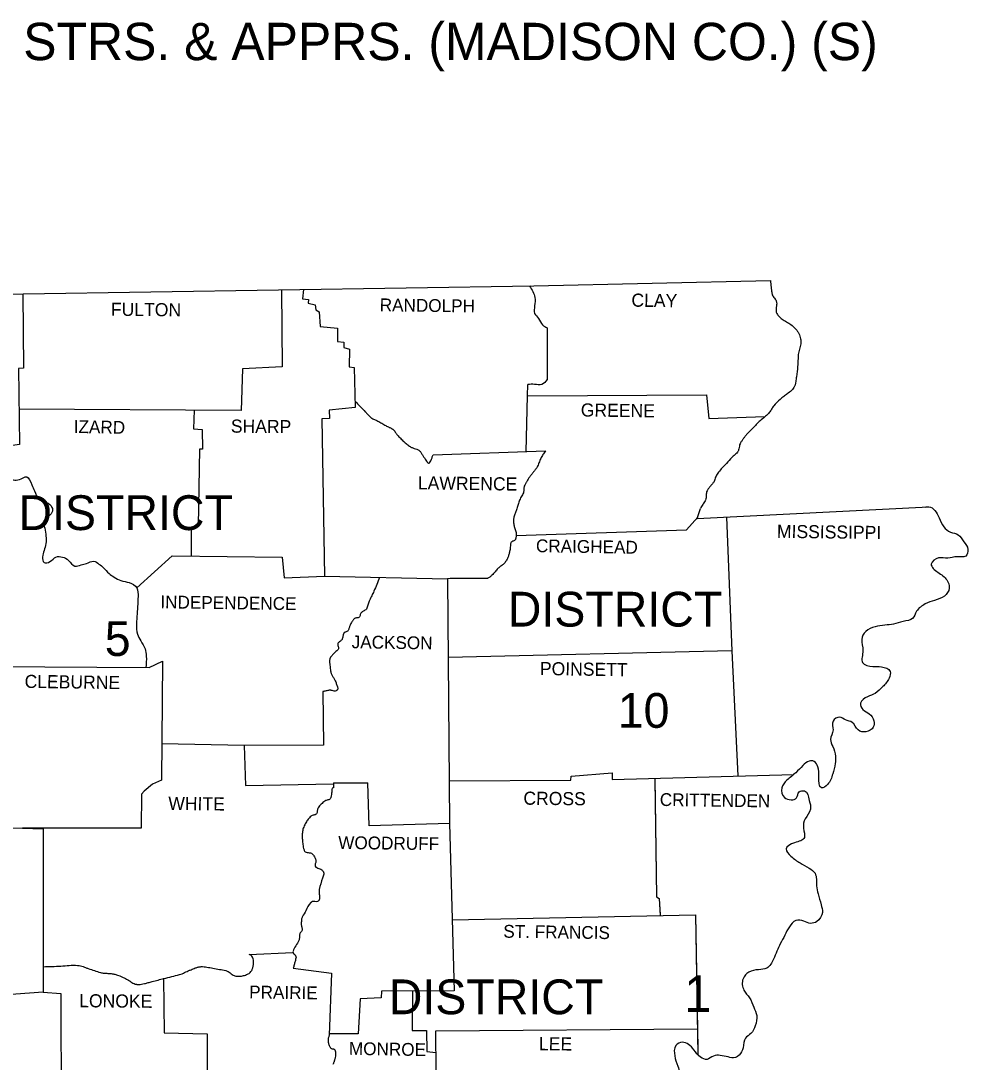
# Model space of a CAD drawing. Extents: x 0 to 3171, y 0 to 2059.
# Drawn here: x 2824.1 to 3134.6, y 1635.7 to 1977.1 of the extents above; entities that cross this region are included whole.
import ezdxf

# ---------------------------------------------------------------- set-up
doc = ezdxf.new("R2010")
doc.units = 0
doc.layers.add('Level 1', color=7, linetype='Continuous')

msp = doc.modelspace()

# ---------------------------------------------------------------- linework, layer by layer
at = {"layer": 'Level 1'}
for p, q in [((2990.18, 1854.23), (2990.27, 1857.93)), ((3045.77, 1813.93), (3046.85, 1817.25)), ((2926.57, 1727.34), (2937.75, 1727.34))]:
    msp.add_line(p, q, dxfattribs=at)
for points in [[(2521.17, 1887.43), (2682.87, 1887.33), (2824.77, 1887.63), (2992.17, 1890.23), (3069.77, 1892.03)], [(2909.47, 1888.95), (2909.67, 1863.73), (2896.67, 1863.03), (2896.27, 1849.43), (2823.43, 1849.84)], [(2916.75, 1889.06), (2916.37, 1886.03), (2918.37, 1885.73), (2918.27, 1884.53), (2920.57, 1884.03), (2920.77, 1882.43), (2921.87, 1881.73), (2922.17, 1876.93), (2927.87, 1876.33), (2927.87, 1872.03), (2929.97, 1871.73), (2929.97, 1870.03), (2931.77, 1869.53), (2931.67, 1863.73), (2933.27, 1863.43), (2933.67, 1850.33), (2925.17, 1849.53), (2925.27, 1846.73), (2922.67, 1846.63), (2923.57, 1795.04), (2963.87, 1794.14), (2964.57, 1713.94), (2938.27, 1713.24), (2937.75, 1727.34)], [(2824.76, 1887.63), (2824.97, 1863.23), (2823.27, 1863.13), (2823.57, 1838.23), (2816.57, 1837.23), (2817.17, 1830.53), (2819.57, 1827.43), (2819.37, 1819.53), (2805.77, 1819.03), (2805.27, 1806.83), (2792.87, 1806.44), (2792.27, 1791.64), (2792.97, 1790.44), (2793.27, 1766.84), (2814.67, 1765.44), (2814.37, 1712.74), (2831.37, 1712.24), (2831.37, 1658.64), (2817.97, 1657.64), (2816.97, 1645.84), (2794.47, 1645.74)], [(2996.57, 1876.43), (2996.57, 1859.53)], [(2989.74, 1835.91), (2990.18, 1854.23), (2990.27, 1854.23), (3048.77, 1854.53), (3049.57, 1846.73), (3067.92, 1847.4)], [(2880.88, 1849.52), (2880.67, 1843.33), (2883.47, 1843.13), (2883.57, 1836.73), (2882.57, 1836.73), (2882.17, 1811.53), (2879.87, 1810.53), (2879.87, 1801.65)], [(2959.17, 1834.83), (2996.04, 1836.13)], [(3045.77, 1813.93), (3121.67, 1817.83)], [(2986.43, 1808.42), (3042.27, 1810.23), (3045.94, 1814.46)], [(3055.35, 1814.43), (3057.07, 1770.54), (3059.1, 1729.57)], [(2862.06, 1791.25), (2873.67, 1801.74), (2909.67, 1801.24), (2910.37, 1794.54), (2923.57, 1795.04)], [(2976.97, 1794.34), (2964.77, 1794.34), (2963.87, 1794.14)], [(3057.07, 1770.54), (2964.09, 1768.42)], [(2814.67, 1765.44), (2866.07, 1765.14), (2870.47, 1767.24), (2870.17, 1728.14), (2867.17, 1726.84), (2864.47, 1724.54), (2863.57, 1723.64), (2863.47, 1712.44), (2824.57, 1712.44)], [(2923.07, 1757.24), (2923.27, 1739.64), (2897.27, 1739.54), (2870.26, 1740.04)], [(2897.27, 1739.54), (2897.67, 1726.44), (2926.57, 1726.95)], [(2964.45, 1727.93), (3004.37, 1728.14), (3004.47, 1729.54), (3017.87, 1730.54), (3017.87, 1728.44), (3077.44, 1730.07)], [(3031.86, 1728.82), (3032.37, 1689.94), (3033.27, 1689.34), (3033.59, 1683.8)], [(3031.87, 1728.44), (3032.37, 1689.94), (3033.27, 1689.34), (3033.57, 1684.14)], [(3031.87, 1728.44), (3032.37, 1689.94), (3033.27, 1689.34), (3033.57, 1684.14)], [(3031.87, 1728.44), (3032.37, 1689.94), (3033.27, 1689.34), (3033.57, 1684.14)], [(3031.87, 1728.44), (3032.37, 1689.94), (3033.27, 1689.34), (3033.57, 1684.14)], [(2926.57, 1727.34), (2926.57, 1725.64), (2926.07, 1725.54)], [(2964.57, 1713.94), (2966.07, 1659.14), (2942.27, 1659.04), (2942.17, 1656.84), (2935.27, 1656.44), (2934.67, 1645.04), (2925.19, 1645.04)], [(2965.43, 1682.43), (3045.17, 1684.04)], [(3045.17, 1684.04), (3045.97, 1640.24)], [(3045.17, 1684.04), (3045.97, 1640.24)], [(3045.17, 1684.04), (3045.97, 1640.24)], [(3045.17, 1684.04), (3045.97, 1640.24)], [(3045.17, 1684.04), (3045.97, 1640.24)], [(3045.17, 1684.04), (3045.97, 1640.24)], [(3045.17, 1684.04), (3045.97, 1640.24)], [(3045.17, 1684.04), (3046.01, 1638.23)], [(2898.87, 1671.04), (2913.26, 1671.73)], [(2913.37, 1666.54), (2925.87, 1664.94), (2925.17, 1644.54)], [(2870.87, 1663.24), (2871.07, 1645.34), (2885.17, 1645.04), (2885.27, 1606.64)], [(2831.37, 1658.64), (2837.17, 1658.24), (2837.27, 1620.04), (2832.07, 1598.34), (2843.17, 1597.84), (2843.07, 1578.73)], [(2952.47, 1659.08), (2952.37, 1646.14), (2956.97, 1646.14), (2957.17, 1639.24), (2960.12, 1638.93)], [(2964.24, 1557.34), (2973.57, 1557.94), (2973.47, 1578.24), (2966.17, 1578.74), (2966.57, 1618.44), (2960.27, 1619.34), (2960.07, 1646.04), (3045.85, 1646.64)]]:
    msp.add_lwpolyline(points, dxfattribs=at)
for points in [[(3069.77, 1892.03), (3069.86, 1890.93), (3069.97, 1889.83), (3070.11, 1888.73), (3070.27, 1887.63), (3070.5, 1887.01), (3070.91, 1886.45), (3071.34, 1885.91), (3071.67, 1885.33), (3071.8, 1884.32), (3071.67, 1883.22), (3071.6, 1882.13), (3071.67, 1881.62), (3071.87, 1881.13), (3072.63, 1880.15), (3073.57, 1879.33), (3074.28, 1878.86), (3075.02, 1878.44), (3075.76, 1878.02), (3076.47, 1877.53), (3077.91, 1876.25), (3078.53, 1875.51), (3078.81, 1875.09), (3079.07, 1874.63), (3079.43, 1873.79), (3079.64, 1872.93), (3079.72, 1872.08), (3079.67, 1871.23), (3079.5, 1870.36), (3079.25, 1869.49), (3079.01, 1868.62), (3078.87, 1867.73), (3078.81, 1866.76), (3078.78, 1865.79), (3078.74, 1864.81), (3078.67, 1863.83), (3078.27, 1860.43), (3078.08, 1858.87), (3077.93, 1858.1), (3077.81, 1857.71), (3077.67, 1857.33), (3076.63, 1855.95), (3075.27, 1854.83), (3074.7, 1854.38), (3074.11, 1853.94), (3073.53, 1853.5), (3072.97, 1853.03), (3070.87, 1850.93), (3070.48, 1850.4), (3070.14, 1849.81), (3069.79, 1849.24), (3069.37, 1848.73), (3066.77, 1846.33), (3064.17, 1843.83), (3062.07, 1841.63), (3061.5, 1840.97), (3060.96, 1840.28), (3060.46, 1839.56), (3059.97, 1838.83), (3059.66, 1838.08), (3059.51, 1837.25), (3059.34, 1836.44), (3059.19, 1836.07), (3058.97, 1835.73), (3058.42, 1835.16), (3057.82, 1834.63), (3057.23, 1834.1), (3056.67, 1833.53), (3054.87, 1831.53), (3052.47, 1828.83), (3052.07, 1828.22), (3051.8, 1827.52), (3051.56, 1826.81), (3051.27, 1826.13), (3050.73, 1825.34), (3050.11, 1824.6), (3049.49, 1823.84), (3048.97, 1823.03), (3048.75, 1822.32), (3048.69, 1821.54), (3048.65, 1820.76), (3048.47, 1820.03), (3048.14, 1819.42), (3047.75, 1818.82), (3047.34, 1818.23), (3046.97, 1817.63), (3046.85, 1817.25)], [(2990.76, 1890.21), (2992.57, 1886.43), (2992.47, 1883.73), (2992.47, 1881.23), (2993.77, 1879.53), (2995.07, 1877.43), (2996.57, 1876.43)], [(2996.57, 1859.53), (2994.87, 1857.93), (2992.37, 1857.93), (2990.27, 1857.93)], [(2933.61, 1852.44), (2935.27, 1850.68), (2936.97, 1848.93), (2937.2, 1848.69), (2937.9, 1847.96), (2938.37, 1847.49), (2938.61, 1847.26), (2938.74, 1847.14), (2938.87, 1847.03), (2939.38, 1846.69), (2939.94, 1846.44), (2940.51, 1846.2), (2941.07, 1845.93), (2942.37, 1845.18), (2943.67, 1844.43), (2944.24, 1844.14), (2944.83, 1843.86), (2945.69, 1843.41), (2945.83, 1843.32), (2945.97, 1843.23), (2946.41, 1842.83), (2946.76, 1842.33), (2947.1, 1841.81), (2947.27, 1841.56), (2947.47, 1841.33), (2948.5, 1840.27), (2949.57, 1839.23), (2950.08, 1838.78), (2950.6, 1838.35), (2951.13, 1837.94), (2951.67, 1837.53), (2952.49, 1837.11), (2953.4, 1836.82), (2954.27, 1836.49), (2954.65, 1836.25), (2954.82, 1836.1), (2954.97, 1835.93), (2955.27, 1835.52), (2955.53, 1835.1), (2955.79, 1834.66), (2956.07, 1834.23), (2956.26, 1833.96), (2956.44, 1833.67), (2956.82, 1833.08), (2957.2, 1832.55), (2957.38, 1832.32), (2957.48, 1832.22), (2957.52, 1832.18), (2957.57, 1832.13), (2957.68, 1832.06), (2957.8, 1832.05), (2958.02, 1832.18), (2958.45, 1832.9), (2958.84, 1833.9), (2959.02, 1834.4), (2959.17, 1834.83)], [(2996.04, 1836.13), (2995.19, 1834.91), (2994.47, 1833.63), (2994.16, 1832.94), (2993.89, 1832.22), (2993.61, 1831.51), (2993.27, 1830.83), (2992.71, 1830.01), (2992.09, 1829.22), (2991.47, 1828.44), (2990.87, 1827.63), (2989.9, 1826.12), (2989.46, 1825.34), (2989.07, 1824.53), (2988.93, 1824.03), (2988.9, 1823.49), (2988.88, 1822.95), (2988.77, 1822.43), (2988.44, 1821.73), (2988.05, 1821.04), (2987.67, 1820.35), (2987.37, 1819.63), (2987.16, 1818.94), (2986.97, 1818.24), (2986.78, 1817.53), (2986.57, 1816.83), (2986.35, 1816.23), (2986.11, 1815.64), (2985.87, 1815.04), (2985.67, 1814.43), (2985.56, 1813.82), (2985.54, 1813.19), (2985.59, 1812.56), (2985.67, 1811.93), (2985.81, 1811.31), (2986.01, 1810.68), (2986.21, 1810.06), (2986.37, 1809.43), (2986.43, 1808.87), (2986.42, 1808.28), (2986.33, 1807.7), (2986.26, 1807.42), (2986.17, 1807.13), (2985.87, 1806.79), (2985.4, 1806.58), (2984.94, 1806.37), (2984.67, 1806.03), (2984.59, 1805.68), (2984.54, 1805.32), (2984.47, 1804.59), (2984.4, 1803.85), (2984.27, 1803.14), (2984.01, 1802.13), (2983.67, 1801.14), (2983.11, 1800.07), (2982.77, 1799.59), (2982.37, 1799.14), (2981.91, 1798.73), (2981.42, 1798.37), (2980.93, 1798.02), (2980.47, 1797.64), (2979.96, 1797.08), (2979.48, 1796.49), (2979, 1795.9), (2978.47, 1795.34), (2977.77, 1794.78), (2977.38, 1794.55), (2976.97, 1794.34)], [(2819.57, 1827.43), (2823.57, 1826.73), (2825.97, 1827.63), (2827.67, 1825.03), (2828.57, 1823.03), (2830.07, 1820.13), (2832.47, 1819.23), (2834.27, 1817.63), (2834.27, 1815.93), (2832.67, 1814.33), (2831.47, 1812.73), (2831.87, 1810.83), (2832.27, 1808.23), (2832.27, 1805.74), (2831.67, 1803.44), (2831.17, 1801.34), (2831.67, 1799.54), (2833.57, 1799.84), (2835.57, 1801.34), (2837.67, 1801.34), (2839.67, 1800.24), (2841.77, 1798.34), (2843.87, 1798.74), (2845.57, 1799.24), (2847.97, 1799.94), (2849.67, 1799.04), (2851.17, 1797.84), (2852.97, 1795.94), (2854.67, 1794.74), (2856.87, 1793.64), (2859.57, 1792.94), (2862.07, 1791.24), (2862.47, 1788.34), (2862.37, 1785.84), (2862.17, 1782.74), (2861.97, 1779.34), (2862.27, 1776.04), (2863.37, 1773.84), (2864.77, 1771.24), (2865.17, 1768.84), (2865.07, 1765.04)], [(3120.57, 1817.73), (3121.67, 1817.83), (3125.07, 1814.23), (3126.57, 1811.23), (3128.77, 1809.53), (3131.27, 1808.63), (3133.17, 1806.34), (3134.47, 1803.84), (3133.77, 1801.64), (3130.97, 1801.44), (3127.87, 1800.94), (3124.87, 1801.04), (3122.47, 1799.04), (3124.67, 1796.34), (3127.57, 1793.84), (3128.37, 1791.14), (3126.77, 1788.54), (3123.57, 1787.14), (3120.47, 1785.94), (3117.67, 1783.54), (3116.37, 1781.24), (3113.27, 1780.24), (3110.07, 1779.34), (3107.27, 1779.04), (3104.07, 1778.44), (3100.97, 1776.94), (3099.67, 1774.34), (3100.07, 1770.64), (3099.97, 1766.74), (3103.27, 1765.44), (3106.17, 1765.34), (3108.97, 1763.84), (3108.67, 1761.64), (3106.57, 1758.84), (3104.07, 1756.64), (3101.57, 1755.54), (3099.27, 1753.44), (3100.07, 1751.34), (3102.17, 1749.94), (3103.67, 1747.64), (3103.47, 1745.54), (3101.07, 1744.04), (3098.47, 1744.64), (3096.57, 1747.14), (3094.37, 1747.94), (3092.47, 1748.84), (3090.27, 1747.54), (3090.27, 1744.64), (3089.47, 1741.54), (3090.17, 1739.24), (3091.07, 1736.04), (3090.97, 1733.64), (3090.17, 1730.24), (3088.47, 1726.74), (3086.47, 1725.64), (3085.67, 1729.44), (3085.27, 1732.54), (3084.07, 1734.34), (3082.47, 1734.44), (3080.37, 1732.94), (3078.07, 1730.64), (3075.17, 1728.14), (3073.47, 1725.64), (3074.37, 1722.54), (3076.57, 1721.74), (3078.27, 1722.34), (3079.17, 1724.34), (3080.87, 1724.64), (3082.47, 1721.54)], [(2941.63, 1794.63), (2940.74, 1792.37), (2939.77, 1790.14), (2939.42, 1789.38), (2939.07, 1788.63), (2938.72, 1787.89), (2938.37, 1787.14), (2938.12, 1786.49), (2937.92, 1785.84), (2937.72, 1785.18), (2937.47, 1784.54), (2937.1, 1784.07), (2936.58, 1783.73), (2936.03, 1783.41), (2935.78, 1783.24), (2935.57, 1783.04), (2935.39, 1782.71), (2935.28, 1782.33), (2935.16, 1781.95), (2934.97, 1781.64), (2934.59, 1781.43), (2934.12, 1781.35), (2933.65, 1781.26), (2933.27, 1781.04), (2933.08, 1780.81), (2932.89, 1780.57), (2932.56, 1780.08), (2932.25, 1779.56), (2931.97, 1779.04), (2931.8, 1778.59), (2931.68, 1778.13), (2931.55, 1777.67), (2931.37, 1777.24), (2931.08, 1776.97), (2930.68, 1776.82), (2930.28, 1776.67), (2929.97, 1776.44), (2929.83, 1776.19), (2929.73, 1775.92), (2929.6, 1775.34), (2929.48, 1774.75), (2929.33, 1774.35), (2929.27, 1774.24), (2928.98, 1773.92), (2928.61, 1773.64), (2928.25, 1773.36), (2927.97, 1773.04), (2927.92, 1772.56), (2928.06, 1772.02), (2928.19, 1771.49), (2928.07, 1771.04), (2927.99, 1770.94), (2927.9, 1770.85), (2927.33, 1770.33), (2926.93, 1770), (2926.57, 1769.64), (2926.23, 1769.27), (2925.89, 1768.89), (2925.59, 1768.49), (2925.47, 1768.27), (2925.37, 1768.04), (2925.25, 1766.94), (2925.37, 1765.84), (2925.44, 1765.11), (2925.53, 1764.38), (2925.66, 1763.65), (2925.75, 1763.29), (2925.87, 1762.94), (2926.08, 1762.49), (2926.35, 1762.07), (2926.62, 1761.66), (2926.87, 1761.24), (2927.36, 1760.14), (2927.57, 1759.59), (2927.77, 1759.04), (2927.88, 1758.68), (2927.95, 1758.3), (2927.9, 1757.94), (2927.81, 1757.78), (2927.75, 1757.7), (2927.67, 1757.64), (2927.05, 1757.4), (2926.43, 1757.46), (2925.79, 1757.61), (2925.48, 1757.65), (2925.17, 1757.64), (2924.64, 1757.55), (2924.12, 1757.46), (2923.59, 1757.36), (2923.07, 1757.24)], [(2926.07, 1725.54), (2926.01, 1724.71), (2925.93, 1723.88), (2925.8, 1723.05), (2925.7, 1722.64), (2925.64, 1722.44), (2925.57, 1722.24), (2925.25, 1721.87), (2924.73, 1721.69), (2924.16, 1721.56), (2923.9, 1721.47), (2923.67, 1721.34), (2922.5, 1720.31), (2921.47, 1719.14), (2921.28, 1718.67), (2921.23, 1718.12), (2921.18, 1717.59), (2920.97, 1717.14), (2920.79, 1716.98), (2920.57, 1716.87), (2920.08, 1716.73), (2919.59, 1716.59), (2919.17, 1716.34), (2918.7, 1715.86), (2918.25, 1715.36), (2917.84, 1714.82), (2917.47, 1714.24), (2916.78, 1712.82), (2916.37, 1711.34), (2916.29, 1709.84), (2916.37, 1708.34), (2916.44, 1707.47), (2916.56, 1706.62), (2916.76, 1705.77), (2916.9, 1705.35), (2917.07, 1704.94), (2917.54, 1704.54), (2918.23, 1704.42), (2918.97, 1704.35), (2919.57, 1704.04), (2919.77, 1703.81), (2919.95, 1703.58), (2920.28, 1703.09), (2920.77, 1702.04), (2920.79, 1701.52), (2920.65, 1700.97), (2920.51, 1700.43), (2920.57, 1699.94), (2921.04, 1699.5), (2921.73, 1699.26), (2922.44, 1699.01), (2922.97, 1698.54), (2923.14, 1698.24), (2923.3, 1697.94), (2923.39, 1697.64), (2923.37, 1697.34), (2922.97, 1696.04), (2921.87, 1692.34), (2921.79, 1691.73), (2921.84, 1691.1), (2921.93, 1690.47), (2921.97, 1689.84), (2921.93, 1689.28), (2921.87, 1689.01), (2921.77, 1688.74), (2921.24, 1688.36), (2920.45, 1688.35), (2919.64, 1688.36), (2919.07, 1688.04), (2917.47, 1685.34), (2916.37, 1683.44), (2916.23, 1683.13), (2916.03, 1682.19), (2915.99, 1681.57), (2915.97, 1680.94), (2916.02, 1680.49), (2916.14, 1680.04), (2916.26, 1679.59), (2916.27, 1679.14), (2916.13, 1678.77), (2915.89, 1678.43), (2915.64, 1678.09), (2915.47, 1677.74), (2915.39, 1677.22), (2915.37, 1676.68), (2915.33, 1676.14), (2915.17, 1675.64), (2914.17, 1673.84), (2913.27, 1672.14), (2913.3, 1671.65), (2913.69, 1671.15), (2914.12, 1670.65), (2914.27, 1670.14), (2914.13, 1669.45), (2913.97, 1668.74), (2913.81, 1668.19), (2913.64, 1667.63), (2913.37, 1666.54)], [(3082.47, 1721.54), (3082.87, 1718.64), (3081.17, 1715.54), (3080.57, 1712.44), (3080.87, 1709.34), (3077.67, 1707.64), (3074.87, 1705.64), (3076.47, 1703.24), (3079.47, 1701.04), (3082.47, 1699.34), (3084.37, 1697.64), (3084.87, 1693.54), (3085.37, 1690.94), (3086.37, 1687.34), (3086.77, 1684.84), (3084.97, 1681.84), (3082.87, 1681.24), (3080.67, 1681.94), (3078.07, 1682.14), (3075.97, 1680.14), (3074.47, 1677.34), (3072.97, 1674.54), (3071.87, 1672.14), (3070.77, 1669.54), (3068.57, 1666.54), (3065.87, 1666.04), (3062.67, 1665.24), (3060.77, 1663.04), (3061.07, 1659.34), (3062.87, 1656.84), (3064.27, 1653.74), (3065.27, 1651.04), (3064.77, 1647.64), (3063.37, 1645.14), (3061.57, 1643.64), (3060.77, 1640.44), (3059.47, 1638.04), (3058.27, 1637.24), (3055.87, 1637.44), (3053.27, 1637.94), (3051.07, 1637.74), (3048.97, 1636.64), (3046.87, 1637.34), (3044.67, 1639.74), (3042.87, 1641.54), (3040.87, 1642.24), (3038.77, 1641.14), (3038.37, 1637.84), (3039.37, 1634.44), (3040.27, 1629.84), (3039.37, 1627.04), (3039.07, 1622.44)], [(2831.37, 1667.03), (2837.17, 1667.24), (2842.67, 1667.44), (2844.44, 1667.09), (2845.3, 1666.75), (2845.74, 1666.59), (2846.17, 1666.44), (2850.17, 1665.14), (2850.74, 1665), (2851.33, 1664.92), (2852.52, 1664.84), (2853.71, 1664.76), (2854.87, 1664.54), (2858.17, 1663.24), (2858.66, 1662.99), (2859.15, 1662.71), (2860.1, 1662.08), (2861.56, 1661.34), (2861.81, 1661.28), (2862.07, 1661.24), (2862.68, 1661.21), (2864.56, 1661.47), (2865.82, 1661.8), (2867.07, 1662.14), (2870.97, 1663.14), (2876.07, 1664.44), (2876.92, 1664.72), (2877.73, 1665.09), (2878.54, 1665.48), (2879.37, 1665.84), (2879.84, 1666.03), (2881.25, 1666.61), (2882.2, 1666.9), (2882.68, 1667), (2883.17, 1667.04), (2885.07, 1666.88), (2886.97, 1666.54), (2889.13, 1666.16), (2891.27, 1665.74), (2891.99, 1665.45), (2892.66, 1664.99), (2893.31, 1664.5), (2893.97, 1664.14), (2895.14, 1663.9), (2896.42, 1663.97), (2897.7, 1664.3), (2898.3, 1664.55), (2898.87, 1664.84), (2899.47, 1665.4), (2899.92, 1666.21), (2900.32, 1668.23), (2899.99, 1670.11), (2899.53, 1670.74), (2898.87, 1671.04)], [(2925.17, 1644.54), (2925.05, 1644.3), (2924.96, 1644.05), (2924.83, 1643.54), (2924.77, 1643.04), (2924.76, 1642.79), (2924.77, 1642.54), (2924.85, 1642), (2925.02, 1641.47), (2925.27, 1640.95), (2925.41, 1640.69), (2925.57, 1640.44), (2925.71, 1640.3), (2925.89, 1640.2), (2926.3, 1640.1), (2926.7, 1640), (2926.86, 1639.9), (2926.92, 1639.83), (2926.97, 1639.74), (2927.02, 1639.62), (2927.06, 1639.49), (2927.22, 1638.74), (2927.23, 1638.24), (2927.21, 1637.99), (2927.17, 1637.74), (2926.97, 1636.73), (2926.84, 1636.23), (2926.76, 1635.99), (2926.67, 1635.74), (2926.49, 1635.33), (2926.27, 1634.94)]]:
    msp.add_spline(points, degree=3, dxfattribs=at)

# ---------------------------------------------------------------- texts
for s, height, p in [('HWY. 23 STRS. & APPRS. (MADISON CO.) (S)', 12.2398, (2754.8, 1964.25)), ('DISTRICT', 11.4, (2823.28, 1810.18)), ('DISTRICT', 11.4, (2983.67, 1778.54)), ('5', 11.4, (2851.56, 1768.9)), ('10', 11.4, (3019.7, 1745.34)), ('DISTRICT', 11.4, (2944.67, 1651.44)), ('1', 12, (3041.47, 1652.14))]:
    msp.add_text(s, height=height, dxfattribs=at).set_placement(p)
for s, height, rotation, p in [('FULTON', 4.299, 359.4996, (2853.57, 1880.43)), ('RANDOLPH', 4.2, 359.2584, (2941.67, 1881.93)), ('CLAY', 4.299, 359.2258, (3024.17, 1883.43)), ('GREENE', 4.301, 359.2361, (3007.57, 1847.43)), ('IZARD', 4.199, 358.9259, (2841.37, 1842.03)), ('SHARP', 4.299, 359.3905, (2892.87, 1842.13)), ('LAWRENCE', 4.301, 359.2678, (2954.17, 1823.53)), ('MISSISSIPPI', 4.2994, 359.3097, (3071.87, 1807.63)), ('CRAIGHEAD', 4.2, 359.1159, (2992.87, 1802.94)), ('INDEPENDENCE', 4.1992, 359.2188, (2869.77, 1784.54)), ('JACKSON', 4.199, 359.1352, (2932.47, 1771.44)), ('POINSETT', 4.299, 359.1987, (2994.17, 1762.64)), ('CLEBURNE', 4.299, 359.2535, (2825.27, 1758.44)), ('CROSS', 4.299, 359.384, (2988.77, 1720.14)), ('WHITE', 4.301, 359.3139, (2872.37, 1718.44)), ('CRITTENDEN', 4.2, 359.213, (3033.47, 1719.74)), ('WOODRUFF', 4.199, 359.2748, (2928.07, 1705.64)), ('ST. FRANCIS', 4.1992, 359.2216, (2982.17, 1676.54)), ('PRAIRIE', 4.2, 359.2116, (2898.87, 1656.64)), ('LONOKE', 4.301, 359.4974, (2843.17, 1653.74)), ('MONROE', 4.199, 359.0331, (2931.57, 1638.14)), ('LEE', 4.301, 359.4327, (2993.87, 1639.64))]:
    msp.add_text(s, height=height, rotation=rotation, dxfattribs=at).set_placement(p)

doc.saveas('drawing.dxf')
